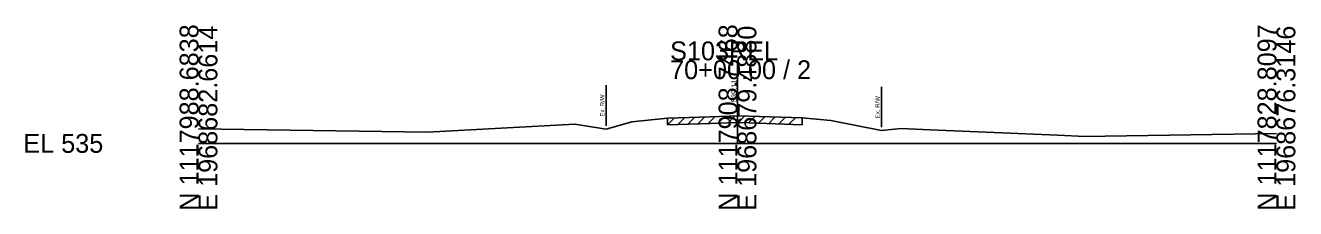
# Model space of a CAD drawing. Extents: x -26 to 163, y -10 to 24518.
# Drawn here: x -25.7 to 162.8, y 18490.3 to 18517.5 of the extents above; entities that cross this region are included whole.
import ezdxf

# ---------------------------------------------------------------- set-up
doc = ezdxf.new("R2010")
doc.units = 0
for name, color, linetype in [('RD_GPK_XS_Cell', 7, 'Continuous'), ('RD_XS_ExGround', 7, 'Continuous'), ('RD_XS_ExPaveRet', 7, 'Continuous'), ('RD_XS_ExRW', 7, 'Continuous'), ('RD_XS_TX_Elev_EX', 7, 'Continuous')]:
    doc.layers.add(name, color=color, linetype=linetype)

msp = doc.modelspace()

# ---------------------------------------------------------------- linework, layer by layer
at = {"layer": 'RD_GPK_XS_Cell'}
for p, q in [((80, 18500), (80, 18512.34)), ((0, 18500), (80, 18500)), ((80, 18500), (160, 18500))]:
    msp.add_line(p, q, dxfattribs=at)
at = {"layer": 'RD_XS_ExGround'}
msp.add_lwpolyline([(0, 18502.15), (33.98, 18501.68), (55.86, 18502.84), (60.51, 18502.13), (64.34, 18503.21), (69.63, 18503.74), (75.97, 18503.96), (80.14, 18504.11), (81.66, 18504.06), (89.61, 18503.77), (93.87, 18503.39), (101.36, 18501.89), (103.33, 18502.1), (104.26, 18502.2), (108.59, 18502.02), (127.49, 18501.22), (131.62, 18501.04), (134.56, 18501.08), (160, 18501.47)], dxfattribs=at)
at = {"layer": 'RD_XS_ExPaveRet'}
for p, q in [((69.63, 18502.74), (70.67, 18503.78)), ((69.63, 18502.74), (69.63, 18503.74)), ((69.63, 18502.74), (75.97, 18502.96)), ((71.13, 18502.79), (72.17, 18503.83)), ((72.63, 18502.85), (73.67, 18503.88)), ((74.13, 18502.9), (75.17, 18503.94)), ((75.63, 18502.95), (76.67, 18503.99)), ((75.97, 18502.96), (80.14, 18503.11)), ((77.13, 18503.01), (78.17, 18504.04)), ((78.63, 18503.06), (79.67, 18504.1)), ((80.13, 18503.11), (81.1, 18504.08)), ((80.14, 18503.11), (81.66, 18503.06)), ((81.63, 18503.06), (82.6, 18504.03)), ((81.66, 18503.06), (89.61, 18502.77)), ((83.13, 18503.01), (84.1, 18503.97)), ((84.63, 18502.95), (85.6, 18503.92)), ((86.13, 18502.9), (87.1, 18503.86)), ((87.63, 18502.84), (88.6, 18503.81)), ((89.61, 18503.77), (89.61, 18502.77))]:
    msp.add_line(p, q, dxfattribs=at)
at = {"layer": 'RD_XS_ExRW'}
for p, q in [((60.51, 18508.63), (60.51, 18502.63)), ((101.36, 18508.39), (101.36, 18502.39))]:
    msp.add_line(p, q, dxfattribs=at)

# ---------------------------------------------------------------- texts
at = {"layer": 'RD_GPK_XS_Cell'}
for s, p in [('N 1117988.6838', (0, 18490)), ('E 1968682.6614', (2.8, 18490)), ('N 1117908.7468', (80, 18490)), ('E 1968679.4880', (82.8, 18490)), ('N 1117828.8097', (160, 18490)), ('E 1968676.3146', (162.8, 18490))]:
    msp.add_text(s, height=2.8, rotation=90, dxfattribs=at).set_placement(p)
for s, p in [('S103REL', (70, 18512.34)), ('70+00.00 / 2', (70, 18509.54)), ('EL 535', (-26, 18498.6))]:
    msp.add_text(s, height=2.8, dxfattribs=at).set_placement(p)
at = {"layer": 'RD_XS_ExRW'}
for p in [(60.26, 18503.97), (101.11, 18503.74)]:
    msp.add_text('Ex. R/W ', height=0.65, rotation=90, dxfattribs=at).set_placement(p)
at = {"layer": 'RD_XS_TX_Elev_EX'}
msp.add_text('539.11', height=0.8, rotation=90, dxfattribs=at).set_placement((79.9, 18506.11))

doc.saveas('drawing.dxf')
